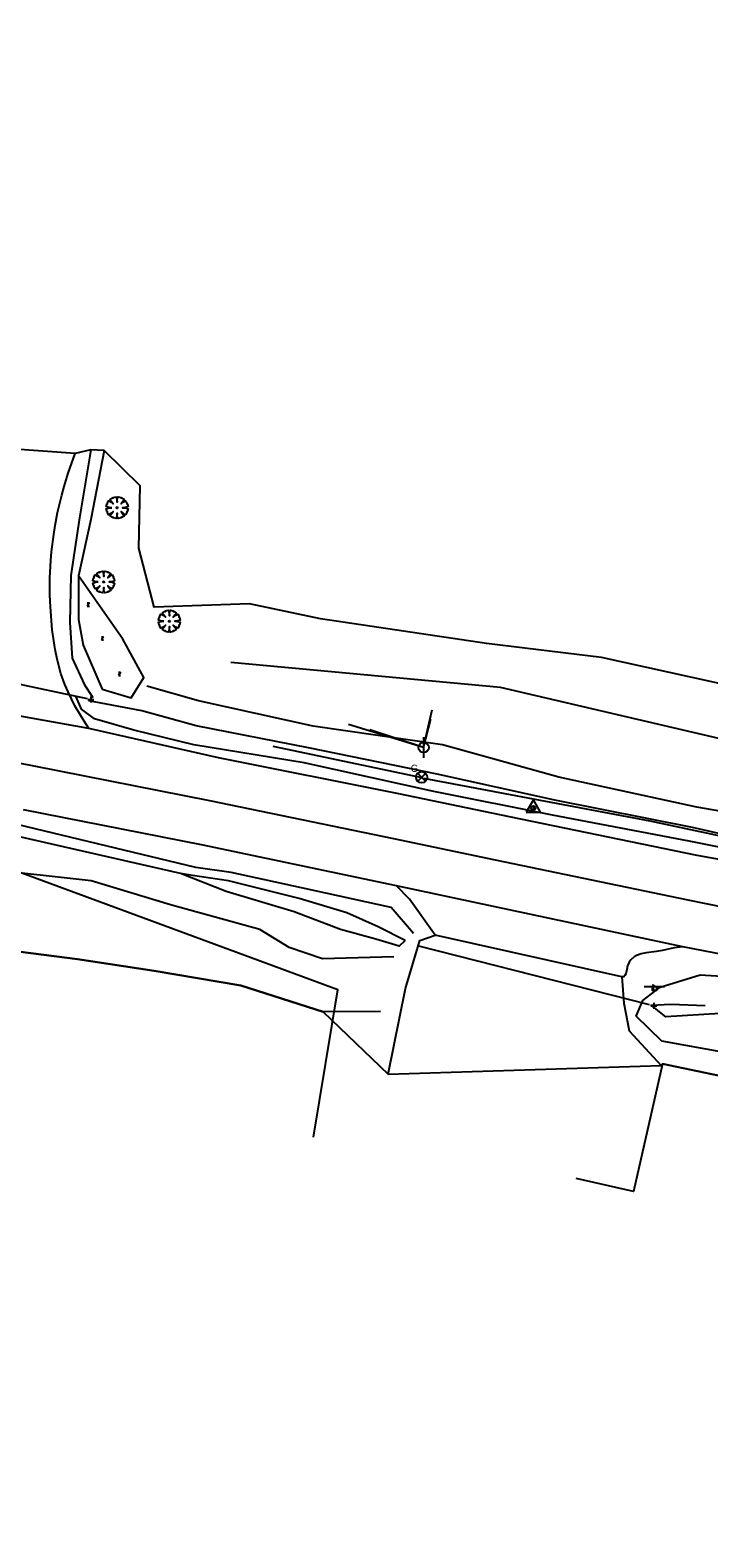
# Model space of a CAD drawing. Extents: x 1158469 to 1165378, y 609843 to 611748.
# Drawn here: x 1164427 to 1164593, y 610055.1 to 610423.9 of the extents above; entities that cross this region are included whole.
import ezdxf

# ---------------------------------------------------------------- set-up
doc = ezdxf.new("R2010")
doc.units = 0
for name, color, linetype in [('Exterior Boundary', 7, 'Continuous'), ('S_Control_Traverse_Point', 7, 'Continuous'), ('S_Drainage_Culvert_Top', 7, 'Continuous'), ('S_Drainage_Ditch_Line', 7, 'Continuous'), ('S_Drainage_Invert', 7, 'Continuous'), ('S_Fencing_ChainLink', 7, 'Continuous'), ('S_Ground_Elevation', 7, 'Continuous'), ('S_Ground_SpotElevation', 7, 'Continuous'), ('S_Property_Garden', 7, 'Continuous'), ('S_Roadway_Centerline', 7, 'Continuous'), ('S_Roadway_Drive_Gravel', 7, 'Continuous'), ('S_Roadway_Drive_Paved', 7, 'Continuous'), ('S_Roadway_Edge_Pavement', 7, 'Continuous'), ('S_Traffic_Sign_SinglePost', 7, 'Continuous'), ('S_Trees_Decid_NonPay', 7, 'Continuous'), ('S_Trees_HedgeLine', 7, 'Continuous'), ('S_Trees_TreeLine', 7, 'Continuous'), ('S_Utilities_Gas_Gate', 7, 'Continuous'), ('S_Utilities_GuyWire3', 7, 'Continuous'), ('S_Utilities_Pole_Power', 7, 'Continuous'), ('S_Utilities_UG_Gas_Line', 7, 'Continuous')]:
    doc.layers.add(name, color=color, linetype=linetype)

msp = doc.modelspace()

# ---------------------------------------------------------------- linework, layer by layer
at = {"layer": 'Exterior Boundary'}
for points in [[(1164600.08, 610263.12), (1164566.81, 610270.51), (1164538.66, 610273.93), (1164498.09, 610279.94), (1164480.73, 610283.61), (1164457.41, 610282.8), (1164453.66, 610297.23), (1164453.93, 610312.49), (1164445.16, 610321.15), (1164441.92, 610321.31), (1164438.04, 610320.35), (1164422.2, 610321.52)], [(1164407.45, 610200.7), (1164438.65, 610196.65), (1164457.36, 610193.85), (1164478.6, 610190.25), (1164498.72, 610183.81), (1164514.58, 610168.55), (1164581.36, 610170.69), (1164581.72, 610171.1), (1164607.36, 610165.71), (1164656.83, 610155.47), (1164687.39, 610149.15), (1164772.52, 610131.34), (1164815.65, 610122.37), (1164871.7, 610110.37), (1164887.39, 610105.37), (1164928.57, 610096.9)]]:
    msp.add_lwpolyline(points, dxfattribs=at)
at = {"layer": 'S_Control_Traverse_Point'}
for p, q in [((1164549.99, 610233.68), (1164550.24, 610233.68)), ((1164550.12, 610233.81), (1164550.12, 610233.56))]:
    msp.add_line(p, q, dxfattribs=at)
msp.add_lwpolyline([(1164548.38, 610232.68), (1164551.85, 610232.68), (1164550.12, 610235.68)], close=True, dxfattribs=at)
msp.add_circle((1164550.12, 610233.68), 0.5, dxfattribs=at)
at = {"layer": 'S_Drainage_Culvert_Top'}
for points in [[(1164441.05, 610260.33), (1164402.69, 610268.54)], [(1164578.55, 610185.47), (1164522.08, 610199.9)]]:
    msp.add_lwpolyline(points, dxfattribs=at)
at = {"layer": 'S_Drainage_Ditch_Line'}
msp.add_lwpolyline([(1164441.92, 610321.31), (1164439.12, 610304.62), (1164437, 610290.51), (1164436.79, 610279), (1164437.36, 610270.31), (1164440.33, 610263.8), (1164442.41, 610260.68)], dxfattribs=at)
at = {"layer": 'S_Drainage_Invert'}
for p, q in [((1164441.12, 610260.19), (1164442.62, 610260.19)), ((1164441.87, 610260.94), (1164441.87, 610259.44)), ((1164579.59, 610186.01), (1164579.59, 610184.51)), ((1164578.84, 610185.26), (1164580.34, 610185.26))]:
    msp.add_line(p, q, dxfattribs=at)
at = {"layer": 'S_Fencing_ChainLink'}
msp.add_lwpolyline([(1164869.51, 610100.35), (1164871.7, 610110.37), (1164815.65, 610122.37), (1164772.52, 610131.34), (1164687.39, 610149.15), (1164656.83, 610155.47), (1164607.36, 610165.71), (1164581.72, 610171.1), (1164574.63, 610139.83), (1164560.56, 610143.01)], dxfattribs=at)
at = {"layer": 'S_Ground_Elevation'}
for points in [[(1164520.77, 610202.93), (1164515.33, 610209.28), (1164493.38, 610214.1), (1164476.21, 610217.89), (1164467.58, 610219.08), (1164423.9, 610229.6), (1164397.15, 610234.48), (1164374.17, 610239.23), (1164343.27, 610245.58), (1164300.5, 610253.79), (1164258.79, 610262.51), (1164217.97, 610271.11), (1164184.42, 610277.79), (1164144.08, 610285.75), (1164112.82, 610291.92), (1164112.71, 610291.96), (1164073.57, 610299.64), (1164023.82, 610309.62), (1163973.46, 610318.76), (1163928.85, 610327.81), (1163885.4, 610335.83), (1163840.61, 610343.96), (1163810.15, 610349.97)], [(1164445.16, 610321.15), (1164441.91, 610304.27), (1164438.91, 610290.46)], [(1164763.58, 610224.84), (1164738.2, 610232.74), (1164717.42, 610239.88), (1164708.24, 610243.35), (1164693.9, 610250.06), (1164675.49, 610248.43), (1164649.1, 610252.28), (1164600.08, 610263.12), (1164566.81, 610270.51), (1164538.66, 610273.93), (1164498.09, 610279.94), (1164480.73, 610283.61), (1164457.41, 610282.8), (1164453.66, 610297.23), (1164453.93, 610312.49)], [(1164512.76, 610183.91), (1164498.72, 610183.81), (1164478.6, 610190.25), (1164457.36, 610193.85), (1164438.65, 610196.65), (1164407.45, 610200.7), (1164368.66, 610206.05), (1164340.53, 610208.91), (1164309.84, 610219.21), (1164290.18, 610222.11), (1164268.68, 610224.9), (1164247.05, 610230.4), (1164220.74, 610233.07), (1164196.76, 610238.37), (1164168.52, 610241.08), (1164148.69, 610246.66), (1164130.83, 610256.24), (1164098.07, 610252.69), (1164038.52, 610254.72), (1164026.83, 610261.83), (1164006.96, 610265.15), (1163992.95, 610262.49), (1163982.22, 610246.79)], [(1164761.29, 610201.44), (1164729.39, 610209.78), (1164702.48, 610212.22), (1164685.33, 610217.31), (1164661.9, 610221.24), (1164620.7, 610228.6), (1164590.08, 610233.86), (1164556.37, 610241.22), (1164527.86, 610249.08), (1164496.26, 610253.68), (1164468.26, 610259.85), (1164455.55, 610263.46)], [(1164758.29, 610189.71), (1164725.91, 610195.8), (1164699.15, 610201.83), (1164659.56, 610210.14), (1164618.3, 610219.54), (1164588.26, 610225.54), (1164554.8, 610231.9), (1164525.78, 610237.71), (1164494.09, 610244.67), (1164467.1, 610249.14), (1164452.39, 610252.67), (1164442.78, 610255.45), (1164439.6, 610257.87), (1164438.33, 610260.82)], [(1164758.56, 610193.13), (1164751.06, 610194.06), (1164726.93, 610199.41), (1164699.99, 610205.18), (1164660.26, 610212.97), (1164618.7, 610222.1), (1164589.01, 610228.9), (1164555.36, 610235.61), (1164526.59, 610241.94), (1164495.09, 610248.39), (1164467.66, 610253.8), (1164454.39, 610257.4), (1164441.36, 610259.91)], [(1164518.74, 610201.23), (1164512.16, 610204.58), (1164504.5, 610207.98), (1164492.86, 610211.52), (1164475.54, 610215.81), (1164466.74, 610217.11), (1164463.83, 610217.64), (1164424.09, 610226.71)], [(1164515.98, 610197.22), (1164498.59, 610196.76), (1164490.4, 610199.54), (1164483.25, 610203.93), (1164461.37, 610209.97), (1164442.01, 610215.81), (1164416.11, 610218.7)], [(1164518.74, 610201.23), (1164517.34, 610199.88), (1164511.57, 610201.59), (1164502.94, 610203.96), (1164491.61, 610208.26), (1164475, 610213.25), (1164463.83, 610217.64)], [(1164937.87, 610100.73), (1164888.97, 610111.32), (1164813.69, 610124.81), (1164773.68, 610135.52), (1164688.09, 610151.59), (1164658.53, 610160.64), (1164609.13, 610171.64), (1164581.57, 610176.61), (1164575.27, 610182.72), (1164576.93, 610186.53), (1164581.1, 610189.86), (1164590.89, 610192.87), (1164600.18, 610192.25)], [(1164946.72, 610105.38), (1164890.19, 610118.57), (1164815.41, 610133.93), (1164775.15, 610140.78), (1164689.92, 610159.35), (1164660.69, 610166.76), (1164611.52, 610180.36), (1164595.78, 610183.41), (1164582.5, 610182.59), (1164578.91, 610185.44), (1164583.71, 610185.64), (1164592.14, 610185.36)]]:
    msp.add_lwpolyline(points, dxfattribs=at)
at = {"layer": 'S_Ground_SpotElevation'}
for p, q in [((1164441.02, 610283.85), (1164441.55, 610283.85)), ((1164441.55, 610283.85), (1164441.02, 610283.06)), ((1164441.02, 610283.06), (1164441.55, 610283.06)), ((1164441.13, 610283.46), (1164441.44, 610283.46)), ((1164444.47, 610275.54), (1164445, 610275.54)), ((1164445, 610275.54), (1164444.47, 610274.76)), ((1164444.47, 610274.76), (1164445, 610274.76)), ((1164444.58, 610275.15), (1164444.89, 610275.15)), ((1164448.66, 610266.85), (1164449.18, 610266.85)), ((1164449.18, 610266.85), (1164448.66, 610266.06)), ((1164448.66, 610266.06), (1164449.18, 610266.06)), ((1164448.76, 610266.46), (1164449.08, 610266.46)), ((1164579.17, 610190.29), (1164579.7, 610190.29)), ((1164579.7, 610190.29), (1164579.17, 610189.5)), ((1164579.17, 610189.5), (1164579.7, 610189.5)), ((1164579.28, 610189.89), (1164579.59, 610189.89))]:
    msp.add_line(p, q, dxfattribs=at)
at = {"layer": 'S_Property_Garden'}
msp.add_lwpolyline([(1164444.68, 610262.77), (1164451.76, 610260.62), (1164454.86, 610265.61), (1164449.75, 610274.98), (1164438.91, 610290.46), (1164438.87, 610279.79), (1164440.04, 610273.47)], close=True, dxfattribs=at)
at = {"layer": 'S_Roadway_Centerline'}
msp.add_lwpolyline([(1165322.92, 610055.12), (1165282.59, 610063.58), (1165267.59, 610066.74), (1165234.97, 610073.48), (1165207.29, 610078.95), (1165170.95, 610086.9), (1165118.3, 610098.03), (1165065.91, 610108.93), (1165025.19, 610117.35), (1164995.59, 610123.89), (1164956.04, 610131.83), (1164919.32, 610140.12), (1164874.11, 610149.34), (1164822.77, 610160.96), (1164779.77, 610169.22), (1164696.7, 610187.78), (1164657.25, 610196.14), (1164616.44, 610205.3), (1164588.01, 610211.13), (1164540.84, 610220.89), (1164515.97, 610226.08), (1164470.96, 610235.38), (1164428.02, 610243.9), (1164400.81, 610249.16)], dxfattribs=at)
at = {"layer": 'S_Roadway_Drive_Gravel'}
for points in [[(1164441.43, 610253.11), (1164440.22, 610254.92), (1164438.01, 610258.67), (1164436.31, 610262.09), (1164435.56, 610263.85), (1164434.59, 610266.55), (1164433.63, 610270.05), (1164433.15, 610272.42), (1164432.47, 610277.22), (1164432, 610282.9), (1164431.89, 610285.73), (1164431.9, 610289.98), (1164432.11, 610294.23), (1164432.29, 610296.35), (1164432.8, 610300.6), (1164433.14, 610302.73), (1164433.75, 610305.92), (1164434.76, 610310.18), (1164435.34, 610312.32), (1164436.33, 610315.53), (1164438.04, 610320.35)], [(1164514.58, 610168.55), (1164518.81, 610189.51), (1164522.37, 610201.24), (1164526.12, 610202.58)], [(1164571.76, 610192.35), (1164572.28, 610185.89), (1164573.58, 610179.16), (1164581.36, 610170.69)]]:
    msp.add_lwpolyline(points, dxfattribs=at)
at = {"layer": 'S_Roadway_Drive_Paved'}
for points in [[(1164586.72, 610199.72), (1164584.55, 610199.44), (1164581.73, 610198.83), (1164580.24, 610198.55), (1164577.7, 610198.21), (1164576.46, 610197.95), (1164575.32, 610197.54), (1164574.81, 610197.26), (1164573.93, 610196.48), (1164573.57, 610195.97), (1164573.17, 610195.03), (1164572.97, 610194.17), (1164572.71, 610193.09), (1164572.51, 610192.67), (1164572.24, 610192.4), (1164572.07, 610192.34), (1164571.76, 610192.35), (1164526.12, 610202.58), (1164519.79, 610211.36), (1164516.67, 610214.63)], [(1165087.67, 610085.66), (1165088.73, 610081.37), (1165088.66, 610075.08), (1165086.95, 610069.17), (1165080.91, 610064.92), (1165078.44, 610064.65), (1165053.51, 610069.94), (1165023.36, 610076.76), (1164985.09, 610084.83), (1164949.13, 610091.57), (1164928.57, 610096.9), (1164887.39, 610105.37), (1164871.7, 610110.37), (1164815.65, 610122.37), (1164772.52, 610131.34), (1164687.39, 610149.15), (1164656.83, 610155.47), (1164607.36, 610165.71), (1164581.72, 610171.1)]]:
    msp.add_lwpolyline(points, dxfattribs=at)
at = {"layer": 'S_Roadway_Edge_Pavement'}
for points in [[(1164919.8, 610151.45), (1164879.24, 610159.72), (1164823.73, 610172.33), (1164795.86, 610178.14), (1164758.26, 610185.55), (1164697.81, 610199.14), (1164659.01, 610207.49), (1164617.87, 610217.04), (1164590.19, 610222.02), (1164544.28, 610231.49), (1164517.23, 610237.09), (1164473.1, 610245.96), (1164441.43, 610253.11), (1164405.39, 610259.57)], [(1164917.37, 610129.44), (1164871.2, 610138.85), (1164820.1, 610150.09), (1164777.51, 610158.77), (1164693.3, 610177.3), (1164655.28, 610185.18), (1164614.45, 610194.3), (1164586.72, 610199.72), (1164516.67, 610214.63), (1164468.95, 610224.66), (1164425.43, 610233.22)]]:
    msp.add_lwpolyline(points, dxfattribs=at)
at = {"layer": 'S_Traffic_Sign_SinglePost'}
msp.add_line((1164577.23, 610189.98), (1164582.23, 610189.98), dxfattribs=at)
msp.add_lwpolyline([(1164579.23, 610189.98), (1164580.23, 610189.98), (1164580.23, 610188.98), (1164579.23, 610188.98)], close=True, dxfattribs=at)
at = {"layer": 'S_Trees_Decid_NonPay'}
for points in [[(1164446.99, 610307.11), (1164446.3, 610307.17), (1164445.66, 610307.38), (1164445.82, 610308.07), (1164445.98, 610308.07), (1164445.93, 610308.28), (1164446.25, 610308.81), (1164446.78, 610308.55), (1164447.36, 610308.07), (1164446.88, 610308.66), (1164446.62, 610309.19), (1164447.15, 610309.51), (1164447.36, 610309.45), (1164447.36, 610309.61), (1164448.05, 610309.77), (1164448.27, 610309.13), (1164448.32, 610308.44), (1164448.37, 610309.13), (1164448.59, 610309.77), (1164449.28, 610309.61), (1164449.28, 610309.45), (1164449.49, 610309.51), (1164450.02, 610309.19), (1164449.75, 610308.66), (1164449.28, 610308.07), (1164449.86, 610308.55), (1164450.39, 610308.81), (1164450.71, 610308.28), (1164450.66, 610308.07), (1164450.82, 610308.07), (1164450.98, 610307.38), (1164450.34, 610307.17), (1164449.65, 610307.11), (1164450.34, 610307.06), (1164450.98, 610306.85), (1164450.82, 610306.16), (1164450.66, 610306.16), (1164450.71, 610305.94), (1164450.39, 610305.41), (1164449.86, 610305.68), (1164449.28, 610306.16), (1164449.75, 610305.57), (1164450.02, 610305.04), (1164449.49, 610304.72), (1164449.28, 610304.78), (1164449.28, 610304.62), (1164448.59, 610304.46), (1164448.37, 610305.09), (1164448.32, 610305.79), (1164448.27, 610305.09), (1164448.05, 610304.46), (1164447.36, 610304.62), (1164447.36, 610304.78), (1164447.15, 610304.72), (1164446.62, 610305.04), (1164446.88, 610305.57), (1164447.36, 610306.16), (1164446.78, 610305.68), (1164446.25, 610305.41), (1164445.93, 610305.94), (1164445.98, 610306.16), (1164445.82, 610306.16), (1164445.66, 610306.85), (1164446.3, 610307.06), (1164446.99, 610307.11)], [(1164443.72, 610288.97), (1164443.03, 610289.02), (1164442.39, 610289.23), (1164442.55, 610289.93), (1164442.71, 610289.93), (1164442.66, 610290.14), (1164442.98, 610290.67), (1164443.51, 610290.4), (1164444.1, 610289.93), (1164443.62, 610290.51), (1164443.35, 610291.04), (1164443.88, 610291.36), (1164444.1, 610291.31), (1164444.1, 610291.47), (1164444.79, 610291.63), (1164445, 610290.99), (1164445.05, 610290.3), (1164445.1, 610290.99), (1164445.32, 610291.63), (1164446.01, 610291.47), (1164446.01, 610291.31), (1164446.22, 610291.36), (1164446.75, 610291.04), (1164446.49, 610290.51), (1164446.01, 610289.93), (1164446.59, 610290.4), (1164447.12, 610290.67), (1164447.44, 610290.14), (1164447.39, 610289.93), (1164447.55, 610289.93), (1164447.71, 610289.23), (1164447.07, 610289.02), (1164446.38, 610288.97), (1164447.07, 610288.92), (1164447.71, 610288.7), (1164447.55, 610288.01), (1164447.39, 610288.01), (1164447.44, 610287.8), (1164447.12, 610287.27), (1164446.59, 610287.53), (1164446.01, 610288.01), (1164446.49, 610287.43), (1164446.75, 610286.9), (1164446.22, 610286.58), (1164446.01, 610286.63), (1164446.01, 610286.47), (1164445.32, 610286.31), (1164445.1, 610286.95), (1164445.05, 610287.64), (1164445, 610286.95), (1164444.79, 610286.31), (1164444.1, 610286.47), (1164444.1, 610286.63), (1164443.88, 610286.58), (1164443.35, 610286.9), (1164443.62, 610287.43), (1164444.1, 610288.01), (1164443.51, 610287.53), (1164442.98, 610287.27), (1164442.66, 610287.8), (1164442.71, 610288.01), (1164442.55, 610288.01), (1164442.39, 610288.7), (1164443.03, 610288.92), (1164443.72, 610288.97)], [(1164459.77, 610279.36), (1164459.08, 610279.41), (1164458.44, 610279.63), (1164458.6, 610280.32), (1164458.76, 610280.32), (1164458.7, 610280.53), (1164459.02, 610281.06), (1164459.55, 610280.8), (1164460.14, 610280.32), (1164459.66, 610280.9), (1164459.4, 610281.43), (1164459.93, 610281.75), (1164460.14, 610281.7), (1164460.14, 610281.86), (1164460.83, 610282.02), (1164461.04, 610281.38), (1164461.1, 610280.69), (1164461.15, 610281.38), (1164461.36, 610282.02), (1164462.05, 610281.86), (1164462.05, 610281.7), (1164462.27, 610281.75), (1164462.8, 610281.43), (1164462.53, 610280.9), (1164462.05, 610280.32), (1164462.64, 610280.8), (1164463.17, 610281.06), (1164463.49, 610280.53), (1164463.43, 610280.32), (1164463.59, 610280.32), (1164463.75, 610279.63), (1164463.12, 610279.41), (1164462.42, 610279.36), (1164463.12, 610279.31), (1164463.75, 610279.1), (1164463.59, 610278.4), (1164463.43, 610278.4), (1164463.49, 610278.19), (1164463.17, 610277.66), (1164462.64, 610277.93), (1164462.05, 610278.4), (1164462.53, 610277.82), (1164462.8, 610277.29), (1164462.27, 610276.97), (1164462.05, 610277.02), (1164462.05, 610276.86), (1164461.36, 610276.7), (1164461.15, 610277.34), (1164461.1, 610278.03), (1164461.04, 610277.34), (1164460.83, 610276.7), (1164460.14, 610276.86), (1164460.14, 610277.02), (1164459.93, 610276.97), (1164459.4, 610277.29), (1164459.66, 610277.82), (1164460.14, 610278.4), (1164459.55, 610277.93), (1164459.02, 610277.66), (1164458.7, 610278.19), (1164458.76, 610278.4), (1164458.6, 610278.4), (1164458.44, 610279.1), (1164459.08, 610279.31), (1164459.77, 610279.36)]]:
    msp.add_lwpolyline(points, dxfattribs=at)
for centre in [(1164448.32, 610307.11), (1164445.05, 610288.97), (1164461.1, 610279.36)]:
    msp.add_circle(centre, 0.167, dxfattribs=at)
at = {"layer": 'S_Trees_HedgeLine'}
msp.add_lwpolyline([(1164631.45, 610242.28), (1164542.05, 610263.12), (1164476.17, 610269.26)], dxfattribs=at)
at = {"layer": 'S_Trees_TreeLine'}
msp.add_lwpolyline([(1164496.37, 610153.1), (1164502.33, 610189.15), (1164371.9, 610237.25), (1164187.56, 610272.44), (1164065.59, 610298.24), (1163909.78, 610326.25), (1163797.57, 610336.57), (1163698.78, 610370.51), (1163500.7, 610405), (1163394.83, 610423.94)], dxfattribs=at)
at = {"layer": 'S_Utilities_Gas_Gate'}
for p, q in [((1164521.83, 610242.14), (1164523.77, 610240.2)), ((1164521.83, 610240.2), (1164523.77, 610242.14))]:
    msp.add_line(p, q, dxfattribs=at)
msp.add_circle((1164522.8, 610241.17), 1.38, dxfattribs=at)
at = {"layer": 'S_Utilities_GuyWire3'}
for points in [[(1164523.29, 610248.47), (1164525.39, 610257.69)], [(1164523.29, 610248.47), (1164504.89, 610254.1)], [(1164523.29, 610248.47), (1164510.14, 610252.76)], [(1164523.29, 610248.47), (1164525.08, 610255.4)]]:
    msp.add_lwpolyline(points, dxfattribs=at)
at = {"layer": 'S_Utilities_Pole_Power'}
msp.add_line((1164523.29, 610250.97), (1164523.29, 610245.97), dxfattribs=at)
msp.add_circle((1164523.29, 610248.47), 1.25, dxfattribs=at)
at = {"layer": 'S_Utilities_UG_Gas_Line'}
for points in [[(1164486.38, 610248.79), (1164522.47, 610241.19)], [(1164523.25, 610240.99), (1164578.61, 610230.52), (1164633.3, 610218.87), (1164687.87, 610206.09), (1164725.23, 610197.92), (1164780.39, 610186.82), (1164833.41, 610174.66), (1164886.88, 610163.44), (1164937.79, 610151.89), (1164988.92, 610140.46), (1164992, 610140.14)]]:
    msp.add_lwpolyline(points, dxfattribs=at)

# ---------------------------------------------------------------- texts
at = {"layer": 'S_Utilities_Gas_Gate'}
msp.add_text('G', height=1.75, dxfattribs=at).set_placement((1164520.12, 610242.5))

doc.saveas('drawing.dxf')
